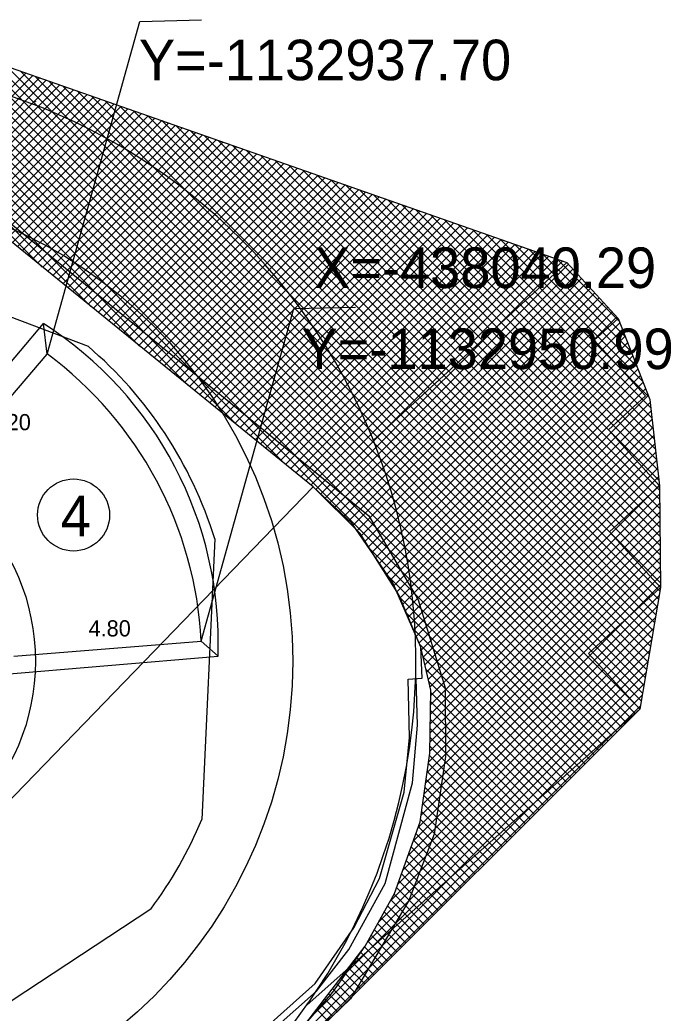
# Model space of a CAD drawing. Extents: x -438410 to -437811, y -1133174 to -1132817.
# Drawn here: x -438048.68 to -438018.55, y -1132968.19 to -1132922.25 of the extents above; entities that cross this region are included whole.
import ezdxf

# ---------------------------------------------------------------- set-up
doc = ezdxf.new("R2010")
doc.units = 0
for name, color, linetype in [('10 - legenda', 7, 'Continuous'), ('Vrstva 1', 7, 'Continuous'), ('Vrstva 5', 7, 'Continuous')]:
    doc.layers.add(name, color=color, linetype=linetype)

msp = doc.modelspace()

# ---------------------------------------------------------------- linework, layer by layer
at = {"layer": '10 - legenda'}
for p, q in [((-438058.378, -1132922.948), (-438047.642, -1132933.684)), ((-438057.898, -1132923.004), (-438045.394, -1132935.507)), ((-438057.418, -1132923.06), (-438043.146, -1132937.331)), ((-438056.938, -1132923.116), (-438040.898, -1132939.155)), ((-438056.458, -1132923.171), (-438038.65, -1132940.979)), ((-438055.978, -1132923.227), (-438036.402, -1132942.803)), ((-438055.497, -1132923.283), (-438022.332, -1132956.448)), ((-438055.017, -1132923.339), (-438022.12, -1132956.236)), ((-438054.537, -1132923.394), (-438021.908, -1132956.024)), ((-438054.057, -1132923.45), (-438021.696, -1132955.812)), ((-438053.577, -1132923.506), (-438021.483, -1132955.6)), ((-438053.097, -1132923.562), (-438021.271, -1132955.388)), ((-438052.617, -1132923.618), (-438021.059, -1132955.176)), ((-438052.137, -1132923.673), (-438020.847, -1132954.964)), ((-438051.657, -1132923.729), (-438020.635, -1132954.752)), ((-438051.177, -1132923.785), (-438020.423, -1132954.539)), ((-438050.605, -1132923.933), (-438020.21, -1132954.327)), ((-438049.952, -1132924.162), (-438020.004, -1132954.109)), ((-438049.298, -1132924.391), (-438019.942, -1132953.747)), ((-438053.018, -1132929.322), (-438048.401, -1132924.705)), ((-438052.784, -1132929.512), (-438048.087, -1132924.815)), ((-438052.55, -1132929.702), (-438047.773, -1132924.925)), ((-438052.315, -1132929.892), (-438047.459, -1132925.035)), ((-438048.645, -1132924.62), (-438019.88, -1132953.385)), ((-438047.992, -1132924.848), (-438019.818, -1132953.022)), ((-438052.081, -1132930.082), (-438047.144, -1132925.146)), ((-438051.847, -1132930.272), (-438046.83, -1132925.256)), ((-438051.613, -1132930.462), (-438046.516, -1132925.366)), ((-438051.379, -1132930.652), (-438046.202, -1132925.476)), ((-438047.339, -1132925.077), (-438019.756, -1132952.66)), ((-438046.686, -1132925.306), (-438019.694, -1132952.298)), ((-438051.144, -1132930.843), (-438045.888, -1132925.586)), ((-438050.91, -1132931.033), (-438045.573, -1132925.696)), ((-438050.676, -1132931.223), (-438045.259, -1132925.806)), ((-438050.442, -1132931.413), (-438044.945, -1132925.916)), ((-438046.033, -1132925.535), (-438019.632, -1132951.935)), ((-438045.38, -1132925.764), (-438019.571, -1132951.573)), ((-438050.207, -1132931.603), (-438044.631, -1132926.026)), ((-438049.973, -1132931.793), (-438044.317, -1132926.136)), ((-438049.739, -1132931.983), (-438044.003, -1132926.246)), ((-438049.505, -1132932.173), (-438043.688, -1132926.356)), ((-438044.727, -1132925.993), (-438019.509, -1132951.211)), ((-438044.074, -1132926.221), (-438019.447, -1132950.848)), ((-438049.27, -1132932.363), (-438043.374, -1132926.467)), ((-438049.036, -1132932.553), (-438043.06, -1132926.577)), ((-438048.802, -1132932.743), (-438042.746, -1132926.687)), ((-438048.568, -1132932.933), (-438042.432, -1132926.797)), ((-438043.421, -1132926.45), (-438019.385, -1132950.486)), ((-438042.767, -1132926.679), (-438019.323, -1132950.124)), ((-438048.334, -1132933.123), (-438042.117, -1132926.907)), ((-438048.099, -1132933.313), (-438041.803, -1132927.017)), ((-438047.865, -1132933.503), (-438041.489, -1132927.127)), ((-438047.631, -1132933.693), (-438041.175, -1132927.237)), ((-438047.397, -1132933.883), (-438040.861, -1132927.347)), ((-438042.114, -1132926.908), (-438019.261, -1132949.761)), ((-438041.461, -1132927.137), (-438019.199, -1132949.399)), ((-438047.162, -1132934.073), (-438040.547, -1132927.457)), ((-438046.928, -1132934.263), (-438040.232, -1132927.567)), ((-438046.694, -1132934.453), (-438039.918, -1132927.677)), ((-438046.46, -1132934.643), (-438039.604, -1132927.788)), ((-438040.808, -1132927.366), (-438019.137, -1132949.037)), ((-438040.155, -1132927.594), (-438019.075, -1132948.674)), ((-438046.225, -1132934.833), (-438039.29, -1132927.898)), ((-438045.991, -1132935.023), (-438038.976, -1132928.008)), ((-438045.757, -1132935.213), (-438038.661, -1132928.118)), ((-438045.523, -1132935.403), (-438038.347, -1132928.228)), ((-438039.502, -1132927.823), (-438019.047, -1132948.278)), ((-438038.849, -1132928.052), (-438019.051, -1132947.85)), ((-438045.288, -1132935.593), (-438038.033, -1132928.338)), ((-438045.054, -1132935.783), (-438037.719, -1132928.448)), ((-438044.82, -1132935.973), (-438037.405, -1132928.558)), ((-438044.586, -1132936.163), (-438037.091, -1132928.668)), ((-438038.196, -1132928.281), (-438019.055, -1132947.422)), ((-438037.543, -1132928.51), (-438019.059, -1132946.994)), ((-438044.352, -1132936.353), (-438036.776, -1132928.778)), ((-438044.117, -1132936.543), (-438036.462, -1132928.888)), ((-438043.883, -1132936.733), (-438036.148, -1132928.998)), ((-438043.649, -1132936.923), (-438035.834, -1132929.109)), ((-438036.89, -1132928.739), (-438019.063, -1132946.565)), ((-438036.236, -1132928.967), (-438019.067, -1132946.137)), ((-438043.415, -1132937.113), (-438035.52, -1132929.219)), ((-438043.18, -1132937.304), (-438035.205, -1132929.329)), ((-438042.946, -1132937.494), (-438034.891, -1132929.439)), ((-438042.712, -1132937.684), (-438034.577, -1132929.549)), ((-438035.583, -1132929.196), (-438019.07, -1132945.709)), ((-438034.93, -1132929.425), (-438019.074, -1132945.281)), ((-438042.478, -1132937.874), (-438034.263, -1132929.659)), ((-438042.243, -1132938.064), (-438033.949, -1132929.769)), ((-438042.009, -1132938.254), (-438033.635, -1132929.879)), ((-438041.775, -1132938.444), (-438033.32, -1132929.989)), ((-438041.541, -1132938.634), (-438033.006, -1132930.099)), ((-438034.277, -1132929.654), (-438019.078, -1132944.853)), ((-438033.624, -1132929.883), (-438019.082, -1132944.425)), ((-438041.306, -1132938.824), (-438032.692, -1132930.209)), ((-438041.072, -1132939.014), (-438032.378, -1132930.319)), ((-438040.838, -1132939.204), (-438032.064, -1132930.43)), ((-438040.604, -1132939.394), (-438031.75, -1132930.54)), ((-438032.971, -1132930.112), (-438019.086, -1132943.997)), ((-438032.318, -1132930.34), (-438019.116, -1132943.543)), ((-438031.665, -1132930.569), (-438019.169, -1132943.065)), ((-438040.37, -1132939.584), (-438031.435, -1132930.65)), ((-438040.135, -1132939.774), (-438031.121, -1132930.76)), ((-438039.901, -1132939.964), (-438030.807, -1132930.87)), ((-438039.667, -1132940.154), (-438030.493, -1132930.98)), ((-438031.012, -1132930.798), (-438019.223, -1132942.587)), ((-438030.359, -1132931.027), (-438019.277, -1132942.109)), ((-438039.433, -1132940.344), (-438030.179, -1132931.09)), ((-438039.198, -1132940.534), (-438029.864, -1132931.2)), ((-438038.964, -1132940.724), (-438029.55, -1132931.31)), ((-438038.73, -1132940.914), (-438029.236, -1132931.42)), ((-438029.706, -1132931.256), (-438019.331, -1132941.631)), ((-438029.052, -1132931.485), (-438019.384, -1132941.153)), ((-438038.496, -1132941.104), (-438028.922, -1132931.53)), ((-438038.261, -1132941.294), (-438028.608, -1132931.64)), ((-438038.027, -1132941.484), (-438028.294, -1132931.751)), ((-438037.793, -1132941.674), (-438027.979, -1132931.861)), ((-438028.399, -1132931.713), (-438019.438, -1132940.675)), ((-438027.746, -1132931.942), (-438019.492, -1132940.197)), ((-438037.559, -1132941.864), (-438027.665, -1132931.971)), ((-438037.324, -1132942.054), (-438027.351, -1132932.081)), ((-438037.09, -1132942.244), (-438027.037, -1132932.191)), ((-438036.856, -1132942.434), (-438026.723, -1132932.301)), ((-438027.093, -1132932.171), (-438019.588, -1132939.676)), ((-438026.44, -1132932.4), (-438019.862, -1132938.978)), ((-438036.622, -1132942.624), (-438026.408, -1132932.411)), ((-438036.388, -1132942.814), (-438026.094, -1132932.521)), ((-438036.153, -1132943.004), (-438025.78, -1132932.631)), ((-438035.919, -1132943.194), (-438025.466, -1132932.741)), ((-438035.685, -1132943.384), (-438025.152, -1132932.851)), ((-438025.787, -1132932.629), (-438020.136, -1132938.28)), ((-438025.134, -1132932.858), (-438020.409, -1132937.582)), ((-438035.451, -1132943.574), (-438024.838, -1132932.961)), ((-438035.216, -1132943.765), (-438024.523, -1132933.072)), ((-438034.994, -1132943.966), (-438024.209, -1132933.182)), ((-438034.78, -1132944.177), (-438023.895, -1132933.292)), ((-438024.481, -1132933.086), (-438020.683, -1132936.884)), ((-438023.828, -1132933.315), (-438020.956, -1132936.187)), ((-438034.567, -1132944.388), (-438023.581, -1132933.402)), ((-438034.354, -1132944.599), (-438023.304, -1132933.55)), ((-438034.14, -1132944.81), (-438023.101, -1132933.771)), ((-438033.927, -1132945.021), (-438022.899, -1132933.992)), ((-438033.714, -1132945.232), (-438022.696, -1132934.214)), ((-438033.5, -1132945.443), (-438022.493, -1132934.435)), ((-438033.287, -1132945.654), (-438022.29, -1132934.656)), ((-438033.074, -1132945.865), (-438022.087, -1132934.878)), ((-438032.878, -1132946.093), (-438021.884, -1132935.099)), ((-438032.714, -1132946.353), (-438021.681, -1132935.32)), ((-438032.55, -1132946.614), (-438021.478, -1132935.542)), ((-438032.386, -1132946.874), (-438021.275, -1132935.763)), ((-438032.222, -1132947.134), (-438021.072, -1132935.984)), ((-438054.642, -1132944.634), (-438047.59, -1132936.293)), ((-438047.411, -1132937.701), (-438047.59, -1132936.293)), ((-438032.058, -1132947.394), (-438020.926, -1132936.263)), ((-438031.893, -1132947.654), (-438020.807, -1132936.568)), ((-438031.729, -1132947.914), (-438020.687, -1132936.872)), ((-438031.565, -1132948.174), (-438020.568, -1132937.177)), ((-438053.084, -1132944.349), (-438047.411, -1132937.701)), ((-438031.401, -1132948.434), (-438020.449, -1132937.482)), ((-438031.237, -1132948.694), (-438020.329, -1132937.787)), ((-438031.09, -1132948.972), (-438020.21, -1132938.091)), ((-438030.965, -1132949.272), (-438020.09, -1132938.396)), ((-438030.841, -1132949.571), (-438019.971, -1132938.701)), ((-438030.716, -1132949.87), (-438019.851, -1132939.006)), ((-438030.591, -1132950.17), (-438019.732, -1132939.311)), ((-438030.466, -1132950.469), (-438019.612, -1132939.615)), ((-438030.341, -1132950.768), (-438019.52, -1132939.947)), ((-438030.216, -1132951.068), (-438019.477, -1132940.329)), ((-438030.107, -1132951.383), (-438019.434, -1132940.71)), ((-438030.027, -1132951.727), (-438019.391, -1132941.092)), ((-438029.947, -1132952.071), (-438019.348, -1132941.473)), ((-438029.866, -1132952.415), (-438019.305, -1132941.854)), ((-438029.786, -1132952.759), (-438019.263, -1132942.236)), ((-438029.706, -1132953.103), (-438019.22, -1132942.617)), ((-438029.679, -1132953.925), (-438019.134, -1132943.38)), ((-438029.673, -1132953.495), (-438019.177, -1132942.999)), ((-438029.685, -1132954.355), (-438019.091, -1132943.761)), ((-438029.691, -1132954.786), (-438019.084, -1132944.179)), ((-438029.697, -1132955.216), (-438019.081, -1132944.599)), ((-438029.703, -1132955.646), (-438019.077, -1132945.02)), ((-438029.709, -1132956.076), (-438019.073, -1132945.44)), ((-438029.768, -1132956.559), (-438019.069, -1132945.861)), ((-438029.838, -1132957.054), (-438019.065, -1132946.281)), ((-438032.48, -1132946.725), (-438022.544, -1132956.66)), ((-438029.909, -1132957.549), (-438019.061, -1132946.702)), ((-438030.051, -1132958.539), (-438019.054, -1132947.542)), ((-438029.98, -1132958.044), (-438019.058, -1132947.122)), ((-438031.754, -1132947.875), (-438022.757, -1132956.872)), ((-438030.121, -1132959.034), (-438019.05, -1132947.963)), ((-438030.258, -1132959.595), (-438019.046, -1132948.383)), ((-438030.495, -1132960.257), (-438019.108, -1132948.87)), ((-438031.097, -1132948.956), (-438022.969, -1132957.084)), ((-438030.733, -1132960.919), (-438019.196, -1132949.382)), ((-438030.793, -1132949.684), (-438023.181, -1132957.297)), ((-438030.971, -1132961.58), (-438019.283, -1132949.893)), ((-438031.208, -1132962.242), (-438019.371, -1132950.405)), ((-438030.489, -1132950.412), (-438023.393, -1132957.509)), ((-438048.965, -1132951.673), (-438040.286, -1132950.986)), ((-438040.288, -1132950.984), (-438039.513, -1132951.677)), ((-438031.557, -1132963.015), (-438019.458, -1132950.917)), ((-438030.185, -1132951.141), (-438023.605, -1132957.721)), ((-438049.786, -1132952.54), (-438039.513, -1132951.677)), ((-438032.091, -1132963.974), (-438019.546, -1132951.429)), ((-438032.626, -1132964.933), (-438019.633, -1132951.94)), ((-438030.028, -1132951.722), (-438023.817, -1132957.933)), ((-438033.882, -1132966.613), (-438019.721, -1132952.452)), ((-438029.899, -1132952.276), (-438024.03, -1132958.145)), ((-438035.278, -1132968.433), (-438019.808, -1132952.964)), ((-438029.77, -1132952.829), (-438024.242, -1132958.357)), ((-438035.275, -1132968.855), (-438019.896, -1132953.476)), ((-438029.671, -1132953.352), (-438024.454, -1132958.569)), ((-438035.066, -1132969.07), (-438019.983, -1132953.987)), ((-438029.677, -1132953.77), (-438024.666, -1132958.781)), ((-438029.683, -1132954.189), (-438024.878, -1132958.993)), ((-438029.689, -1132954.607), (-438025.091, -1132959.205)), ((-438029.695, -1132955.026), (-438025.303, -1132959.417)), ((-438029.7, -1132955.444), (-438025.515, -1132959.629)), ((-438029.726, -1132956.267), (-438025.939, -1132960.054)), ((-438029.706, -1132955.862), (-438025.727, -1132959.841)), ((-438029.779, -1132956.638), (-438026.152, -1132960.266)), ((-438029.832, -1132957.009), (-438026.364, -1132960.478)), ((-438029.885, -1132957.381), (-438026.576, -1132960.69)), ((-438029.991, -1132958.123), (-438027, -1132961.114)), ((-438029.938, -1132957.752), (-438026.788, -1132960.902)), ((-438030.044, -1132958.494), (-438027.212, -1132961.326)), ((-438030.097, -1132958.865), (-438027.425, -1132961.538)), ((-438030.15, -1132959.237), (-438027.637, -1132961.75)), ((-438030.359, -1132959.877), (-438028.061, -1132962.174)), ((-438030.247, -1132959.564), (-438027.849, -1132961.962)), ((-438030.471, -1132960.189), (-438028.273, -1132962.386)), ((-438030.695, -1132960.813), (-438028.698, -1132962.811)), ((-438030.583, -1132960.501), (-438028.486, -1132962.598)), ((-438030.807, -1132961.125), (-438028.91, -1132963.023)), ((-438031.031, -1132961.75), (-438029.334, -1132963.447)), ((-438030.919, -1132961.438), (-438029.122, -1132963.235)), ((-438031.143, -1132962.062), (-438029.546, -1132963.659)), ((-438031.371, -1132962.682), (-438029.971, -1132964.083)), ((-438031.255, -1132962.374), (-438029.759, -1132963.871)), ((-438031.523, -1132962.955), (-438030.183, -1132964.295)), ((-438031.827, -1132963.5), (-438030.607, -1132964.719)), ((-438031.675, -1132963.227), (-438030.395, -1132964.507)), ((-438032.131, -1132964.045), (-438031.032, -1132965.143)), ((-438031.979, -1132963.772), (-438030.82, -1132964.931)), ((-438032.283, -1132964.317), (-438031.244, -1132965.355)), ((-438032.586, -1132964.862), (-438031.668, -1132965.78)), ((-438032.434, -1132964.589), (-438031.456, -1132965.568)), ((-438032.928, -1132965.369), (-438032.093, -1132966.204)), ((-438032.743, -1132965.129), (-438031.881, -1132965.992)), ((-438033.296, -1132965.849), (-438032.517, -1132966.628)), ((-438033.112, -1132965.609), (-438032.305, -1132966.416)), ((-438033.664, -1132966.329), (-438032.941, -1132967.052)), ((-438033.48, -1132966.089), (-438032.729, -1132966.84)), ((-438034.033, -1132966.81), (-438033.366, -1132967.476)), ((-438033.848, -1132966.569), (-438033.154, -1132967.264)), ((-438034.401, -1132967.29), (-438033.79, -1132967.9)), ((-438034.217, -1132967.05), (-438033.578, -1132967.688)), ((-438034.769, -1132967.77), (-438034.215, -1132968.325)), ((-438034.585, -1132967.53), (-438034.002, -1132968.112)), ((-438034.953, -1132968.01), (-438034.427, -1132968.537))]:
    msp.add_line(p, q, dxfattribs=at)
for points in [[(-438047.411, -1132937.701), (-438043.135, -1132922.318), (-438040.271, -1132922.246)], [(-438073.176, -1132952.717), (-438056.752, -1132966.178), (-438035.111, -1132943.85), (-438055.747, -1132927.108), (-438057.633, -1132926.12), (-438061.247, -1132924.998), (-438062.981, -1132924.836), (-438065.997, -1132924.747)], [(-438040.288, -1132950.984), (-438036.012, -1132935.601), (-438033.148, -1132935.529)], [(-438047.351, -1132977.847), (-438035.024, -1132966.82), (-438033.236, -1132964.241), (-438032.047, -1132961.955), (-438030.901, -1132957.963), (-438030.66, -1132955.437), (-438030.712, -1132952.747), (-438030.075, -1132952.687), (-438030.136, -1132951.258), (-438031.431, -1132948.289), (-438033.325, -1132945.529), (-438035.111, -1132943.85), (-438056.752, -1132966.178), (-438056.391, -1132966.651), (-438056.287, -1132967.153), (-438056.447, -1132967.73), (-438057.085, -1132968.345)], [(-438063.708, -1132995.286), (-438064.515, -1132994.394), (-438035.457, -1132968.667), (-438034.209, -1132967.217), (-438032.713, -1132965.089), (-438031.357, -1132962.656), (-438030.164, -1132959.335), (-438029.71, -1132956.158), (-438029.67, -1132953.257), (-438030.136, -1132951.258)], [(-438073.738, -1133001.559), (-438034.962, -1132967.179), (-438033.461, -1132965.239), (-438031.779, -1132962.199), (-438030.513, -1132957.537), (-438030.279, -1132954.87), (-438030.35, -1132952.695)]]:
    msp.add_lwpolyline(points, dxfattribs=at)
msp.add_lwpolyline([(-438064.046, -1132923.967), (-438059.054, -1132922.87), (-438050.953, -1132923.811), (-438023.373, -1132933.474), (-438021.008, -1132936.054), (-438019.535, -1132939.812), (-438019.088, -1132943.791), (-438019.045, -1132948.5), (-438020.007, -1132954.124), (-438035.014, -1132969.123), (-438035.457, -1132968.667), (-438032.713, -1132965.089), (-438031.357, -1132962.656), (-438030.164, -1132959.335), (-438029.71, -1132956.158), (-438029.67, -1132953.257), (-438030.136, -1132951.258), (-438031.147, -1132948.836), (-438032.937, -1132946), (-438035.111, -1132943.85), (-438055.747, -1132927.108), (-438057.633, -1132926.12), (-438061.247, -1132924.998), (-438064.1, -1132924.747)], close=True, dxfattribs=at)
msp.add_circle((-438046.198, -1132945.147), 1.666, dxfattribs=at)
for centre, radius, start, end in [((-438057.031, -1132951.062), 17.529, 357.988, 57.4099), ((-438057.963, -1132951.911), 17.7, 3.0018, 53.4108)]:
    msp.add_arc(centre, radius, start, end, dxfattribs=at)
at = {"layer": 'Vrstva 1'}
for p, q in [((-438057.684, -1132932.736), (-438045.528, -1132937.343)), ((-438039.668, -1132946.245), (-438040.266, -1132959.231)), ((-438042.628, -1132963.381), (-438053.487, -1132970.529))]:
    msp.add_line(p, q, dxfattribs=at)
msp.add_lwpolyline([(-438035.397, -1132967.806), (-438020.007, -1132954.124), (-438022.369, -1132951.547), (-438019.045, -1132948.5), (-438021.41, -1132945.92), (-438019.088, -1132943.791), (-438021.453, -1132941.211), (-438019.741, -1132939.641), (-438022.106, -1132937.061), (-438021.008, -1132936.054), (-438023.373, -1132933.474), (-438032.328, -1132941.683)], dxfattribs=at)
for centre, radius in [((-438047.97, -1132926.032), 0.0127), ((-438047.97, -1132926.032), 0.0127), ((-438057.962, -1132951.913), 21.902), ((-438057.962, -1132951.913), 10)]:
    msp.add_circle(centre, radius, dxfattribs=at)
for centre, radius, start, end in [((-438057.962, -1132951.913), 27.6, 21.7557, 127.458), ((-438057.961, -1132951.909), 19.15, 17.2035, 49.5162), ((-438057.962, -1132951.913), 27.6, 324.841, 21.8954), ((-438057.961, -1132951.909), 19.15, 323.2167, 337.5192), ((-438057.962, -1132951.913), 27.6, 285.1936, 325.11)]:
    msp.add_arc(centre, radius, start, end, dxfattribs=at)
at = {"layer": 'Vrstva 5'}
msp.add_lwpolyline([(-438100.102, -1132946.562), (-438096.145, -1132946.087), (-438076.81, -1132928.968), (-438073.152, -1132926.415), (-438070.224, -1132924.975), (-438066.296, -1132924.11), (-438061.467, -1132924.187), (-438057.913, -1132925.24), (-438055.399, -1132926.536), (-438032.541, -1132945.181), (-438030.254, -1132949.067), (-438029.004, -1132953.142), (-438028.985, -1132956.312), (-438029.517, -1132959.914), (-438030.683, -1132962.977), (-438031.923, -1132965.059), (-438033.387, -1132967.52), (-438034.269, -1132968.372), (-438043.912, -1132976.82)], dxfattribs=at)

# ---------------------------------------------------------------- texts
at = {"layer": '10 - legenda'}
for s, p in [('Y=-1132937.70', (-438043.171, -1132925.039)), ('X=-438040.29', (-438035.07, -1132934.648)), ('Y=-1132950.99', (-438035.652, -1132938.398))]:
    msp.add_text(s, height=1.875, rotation=360, dxfattribs=at).set_placement(p)
for s, height, p in [('5.20 ', 0.75, (-438050.125, -1132941.228)), ('4', 1.875, (-438046.79, -1132946.136)), ('4.80 ', 0.75, (-438045.502, -1132950.765))]:
    msp.add_text(s, height=height, dxfattribs=at).set_placement(p)

doc.saveas('drawing.dxf')
